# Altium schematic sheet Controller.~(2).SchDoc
size A
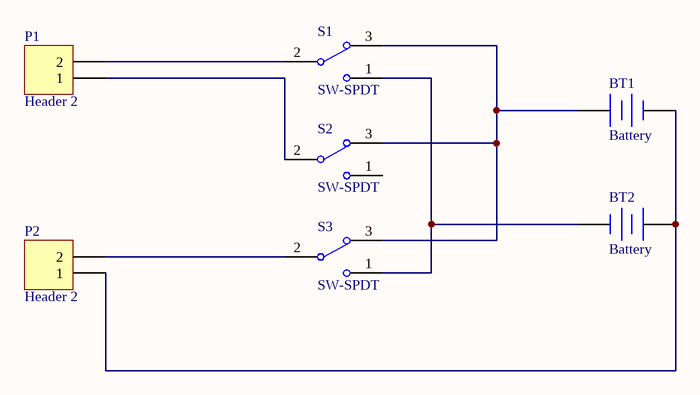
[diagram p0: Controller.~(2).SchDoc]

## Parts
BT1  Battery  [BAT-2]
BT2  Battery  [BAT-2]
P1  Header 2  [HDR1X2]
P2  Header 2  [HDR1X2]
S1  SW-SPDT  [TL36WW15050]
S2  SW-SPDT  [TL36WW15050]
S3  SW-SPDT  [TL36WW15050]

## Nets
NetBT1_1: BT1.1(+) S1.3 S2.3 S3.3
NetBT1_2: BT1.2(-) BT2.1(+) P2.1
NetBT2_2: BT2.2(-) S1.1 S3.1
NetP1_1: P1.1 S2.2
NetP1_2: P1.2 S1.2
NetP2_2: P2.2 S3.2

Not connected (* = marked no-connect by the designer): S2 1

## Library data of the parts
BT1 BT2 = Battery: Multicell Battery
P1 P2 = Header 2: Header, 2-Pin
S1-S3 = SW-SPDT: SPDT Subminiature Toggle Switch, Right Angle Mounting, Vertical Actuation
